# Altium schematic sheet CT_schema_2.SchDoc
size 461 x 297 mm
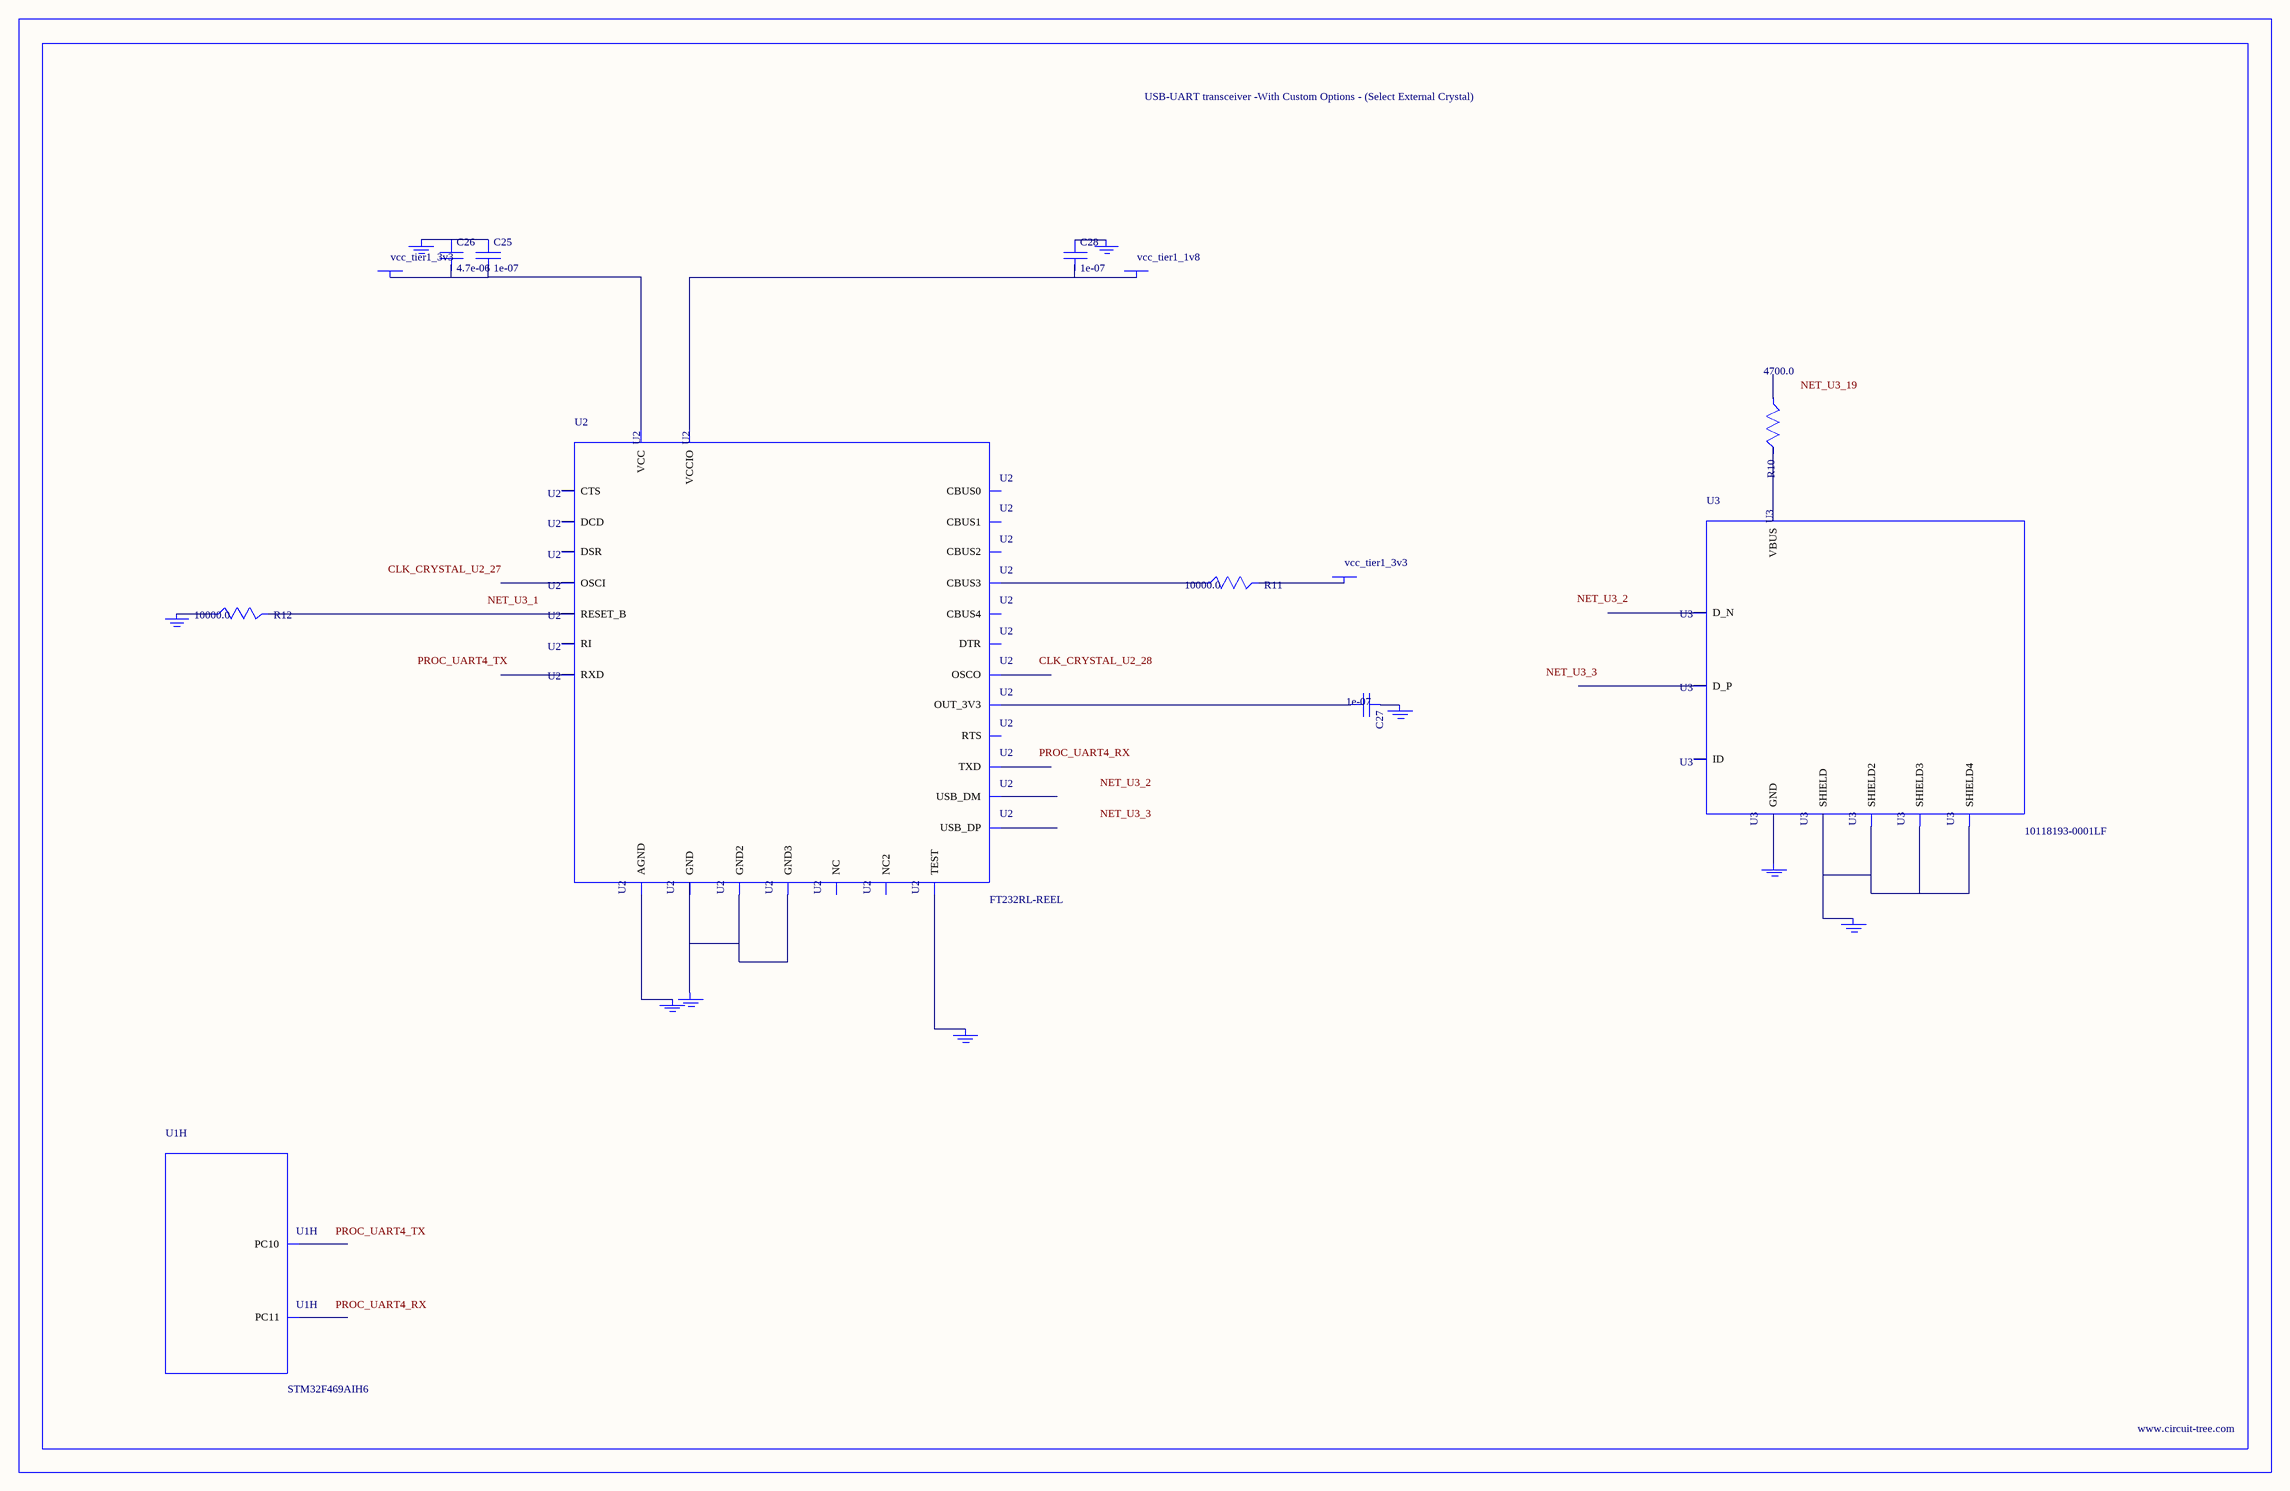
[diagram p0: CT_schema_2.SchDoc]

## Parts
BORDER1  (no value)
C25  1e-07  [C0402]
C26  4.7e-06  [C0805]
C27  1e-07  [C0402]
C28  1e-07  [C0402]
GND_INSTANCE_1_0  (no value)
GND_INSTANCE_1_1  (no value)
GND_INSTANCE_1_2  (no value)
GND_INSTANCE_1_3  (no value)
GND_INSTANCE_1_4  (no value)
GND_INSTANCE_1_5  (no value)
GND_INSTANCE_1_6  (no value)
GND_INSTANCE_1_7  (no value)
GND_INSTANCE_1_8  (no value)
POWER_INSTANCE_1_0  vcc_tier1_1v8
POWER_INSTANCE_1_1  vcc_tier1_3v3
POWER_INSTANCE_1_2  vcc_tier1_3v3
R10  4700.0  [R0603]
R11  10000.0  [R0603]
R12  10000.0  [R0603]
U1  STM32F469AIH6  [UFBGA169]  (part H of 13)
U2  FT232RL-REEL  [SSOP-28]
U3  10118193-0001LF  [FCI_10118193-0001LF]

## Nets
NetC25_1: C25.1 C26.1 GND_INSTANCE_1_3.0(GND)
NetC25_2: C25.2 C26.2 POWER_INSTANCE_1_2.0(PWR) U2.20(VCC)
NetC27_1: C27.1 GND_INSTANCE_1_1.0(GND)
NetC27_2: C27.2 U2.17(OUT_3V3)
NetC28_1: C28.1 GND_INSTANCE_1_0.0(GND)
NetC28_2: C28.2 POWER_INSTANCE_1_0.0(PWR) U2.4(VCCIO)
NetGND_INSTANCE_1_2_0: GND_INSTANCE_1_2.0(GND) R12.1
NetGND_INSTANCE_1_4_0: GND_INSTANCE_1_4.0(GND) U2.25(AGND)
NetGND_INSTANCE_1_5_0: GND_INSTANCE_1_5.0(GND) U2.26(TEST)
NetGND_INSTANCE_1_6_0: GND_INSTANCE_1_6.0(GND) U2.7(GND) U2.18(GND2) U2.21(GND3)
NetGND_INSTANCE_1_7_0: GND_INSTANCE_1_7.0(GND) U3.6(SHIELD) U3.7(SHIELD2) U3.8(SHIELD3) U3.9(SHIELD4)
NetGND_INSTANCE_1_8_0: GND_INSTANCE_1_8.0(GND) U3.5(GND)
NetPOWER_INSTANCE_1_1_0: POWER_INSTANCE_1_1.0(PWR) R11.2
NetR10_2: R10.2 U3.1(VBUS)
NetR11_1: R11.1 U2.14(CBUS3)
NetR12_2: R12.2 U2.19(RESET_B)

Not connected (* = marked no-connect by the designer): R10 1; U1 B9(PC11) C10(PC10); U2 1(TXD) 2(DTR) 3(RTS) 5(RXD) 6(RI) 8(NC) 9(DSR) 10(DCD) 11(CTS) 12(CBUS4) 13(CBUS2) 15(USB_DP) 16(USB_DM) 22(CBUS1) 23(CBUS0) 24(NC2) 27(OSCI) 28(OSCO); U3 2(D_N) 3(D_P) 4(ID)

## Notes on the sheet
- Labels drawn without touching a wire or pin: CLK_CRYSTAL_U2_27, CLK_CRYSTAL_U2_28, NET_U3_1, NET_U3_2, NET_U3_3, NET_U3_19, PROC_UART4_RX, PROC_UART4_TX

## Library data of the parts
BORDER1 = BORDER_PAGE1
C25 C27 C28 = C0402C104K3RACTU
C26 = C0805C475K4RACTU
GND_INSTANCE_1_0-GND_INSTANCE_1_8 = GND
POWER_INSTANCE_1_0-POWER_INSTANCE_1_2 = PWR
R10 = RC0603JR-074K7L
R11 R12 = RC0603JR-0710KL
